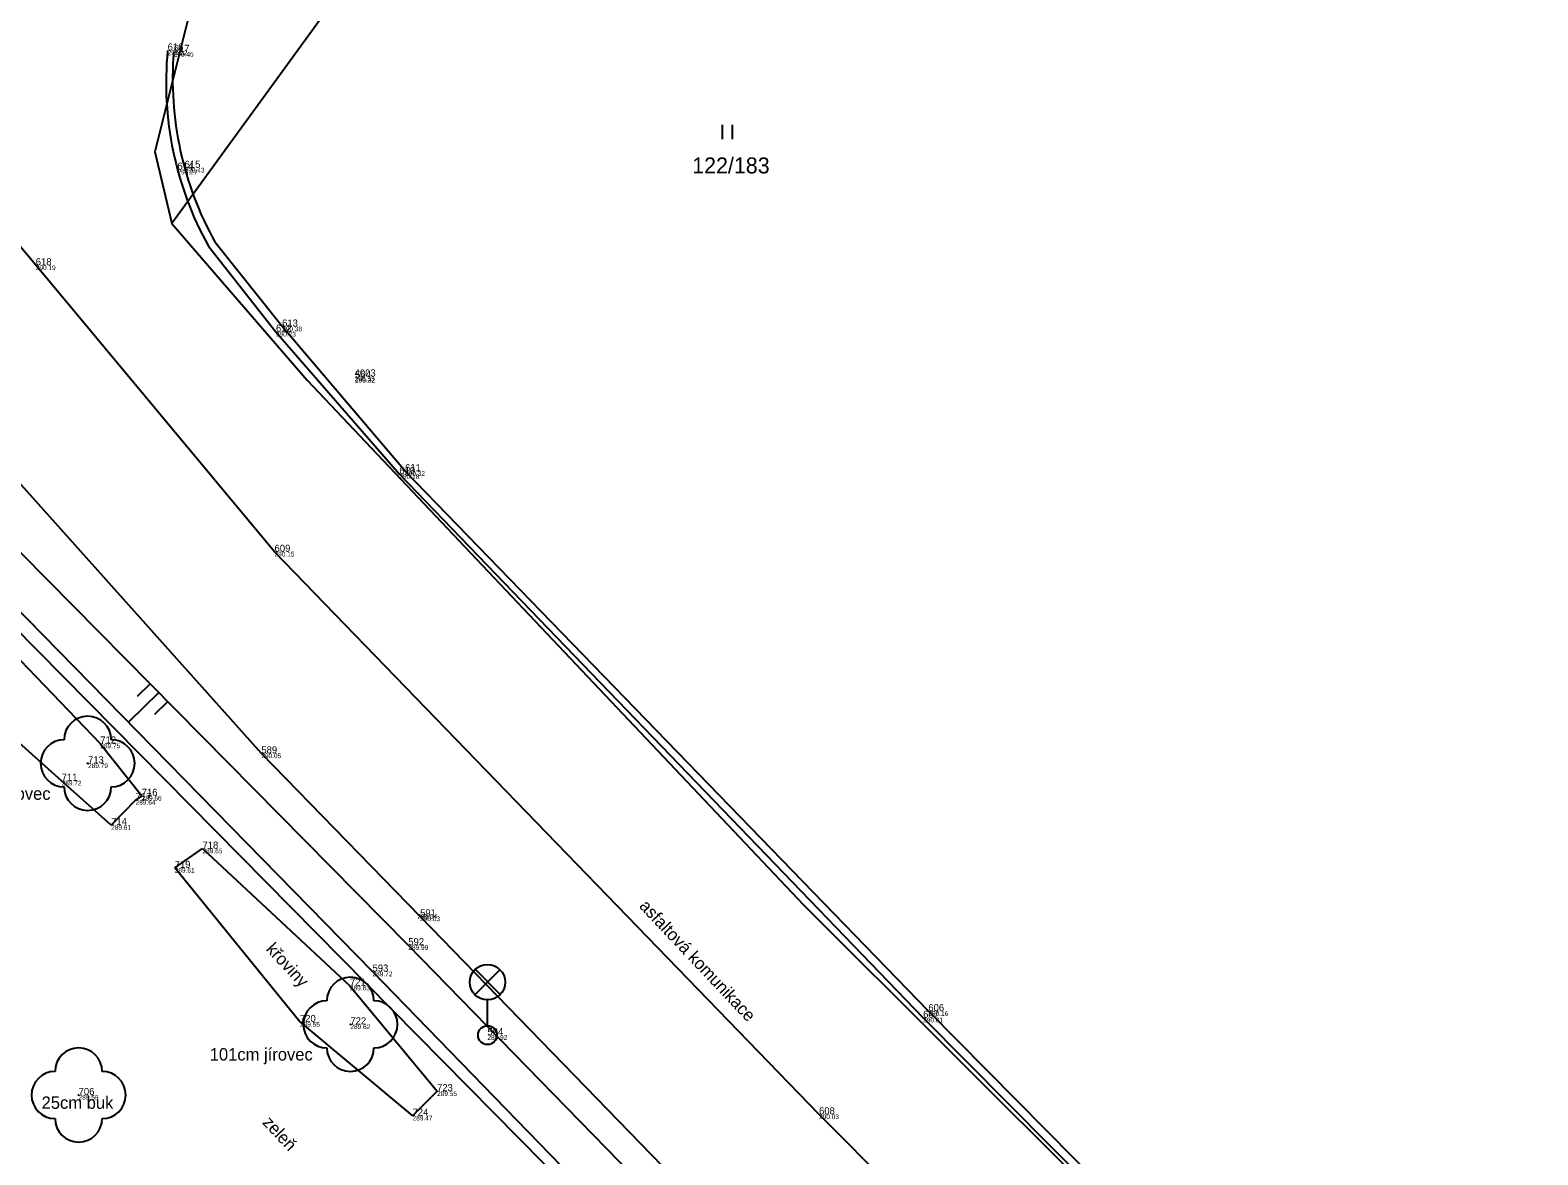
# Model space of a CAD drawing. Extents: x -805057 to -804930, y -994399 to -994240.
# Drawn here: x -804979.61 to -804947.6, y -994315.23 to -994291.36 of the extents above; entities that cross this region are included whole.
import ezdxf

# ---------------------------------------------------------------- set-up
doc = ezdxf.new("R2010")
doc.units = 0
for name, color, linetype in [('bod cislo', 7, 'Continuous'), ('bod pozice', 7, 'Continuous'), ('bod výška', 7, 'Continuous'), ('Katastralni mapa', 7, 'Continuous'), ('komunikace', 7, 'Continuous'), ('lampa', 7, 'Continuous'), ('plot', 7, 'Continuous'), ('popis', 7, 'Continuous'), ('strom', 7, 'Continuous'), ('svah', 7, 'Continuous'), ('šrafy', 7, 'Continuous')]:
    doc.layers.add(name, color=color, linetype=linetype)

msp = doc.modelspace()

# ---------------------------------------------------------------- linework, layer by layer
at = {"layer": 'bod pozice'}
for p, q in [((-804976.69, -994291.79), (-804976.69, -994291.79)), ((-804976.56, -994291.82), (-804976.56, -994291.82)), ((-804976.48, -994294.32), (-804976.48, -994294.32)), ((-804976.33, -994294.28), (-804976.33, -994294.28)), ((-804979.49, -994296.35), (-804979.49, -994296.35)), ((-804974.39, -994297.76), (-804974.39, -994297.76)), ((-804974.26, -994297.65), (-804974.26, -994297.65)), ((-804972.72, -994298.71), (-804972.72, -994298.71)), ((-804972.71, -994298.74), (-804972.71, -994298.74)), ((-804971.77, -994300.78), (-804971.77, -994300.78)), ((-804971.65, -994300.72), (-804971.65, -994300.72)), ((-804974.42, -994302.43), (-804974.42, -994302.43)), ((-804978.12, -994306.5), (-804978.12, -994306.5)), ((-804974.7, -994306.71), (-804974.7, -994306.71)), ((-804978.38, -994306.92), (-804978.38, -994306.92)), ((-804978.94, -994307.29), (-804978.94, -994307.29)), ((-804977.37, -994307.7), (-804977.37, -994307.7)), ((-804977.24, -994307.61), (-804977.24, -994307.61)), ((-804977.89, -994308.23), (-804977.89, -994308.23)), ((-804975.95, -994308.73), (-804975.95, -994308.73)), ((-804976.54, -994309.14), (-804976.54, -994309.14)), ((-804971.33, -994310.17), (-804971.33, -994310.17)), ((-804971.58, -994310.78), (-804971.58, -994310.78)), ((-804972.34, -994311.34), (-804972.34, -994311.34)), ((-804972.82, -994311.64), (-804972.82, -994311.64)), ((-804960.65, -994312.32), (-804960.65, -994312.32)), ((-804960.54, -994312.18), (-804960.54, -994312.18)), ((-804973.88, -994312.41), (-804973.88, -994312.41)), ((-804972.81, -994312.46), (-804972.81, -994312.46)), ((-804969.9, -994312.69), (-804969.9, -994312.69)), ((-804970.97, -994313.88), (-804970.97, -994313.88)), ((-804978.58, -994313.96), (-804978.58, -994313.96)), ((-804971.49, -994314.4), (-804971.49, -994314.4)), ((-804962.86, -994314.37), (-804962.86, -994314.37))]:
    msp.add_line(p, q, dxfattribs=at)
at = {"layer": 'Katastralni mapa'}
for points in [[(-804950.9, -994260.129), (-804976.6, -994295.46)], [(-804976.25, -994291.08), (-804976.96, -994293.94), (-804976.6, -994295.46)], [(-804964.907, -994293.67), (-804964.907, -994293.37)], [(-804964.7, -994293.67), (-804964.7, -994293.37)], [(-804976.6, -994295.46), (-804973.73, -994298.79), (-804963.19, -994309.92)], [(-804953.13, -994331.19), (-804983.74, -994300.19)], [(-804963.19, -994309.92), (-804950.9, -994322.183)]]:
    msp.add_lwpolyline(points, dxfattribs=at)
at = {"layer": 'komunikace'}
for p, q in [((-804979.49, -994296.35), (-804983.16, -994291.96)), ((-804975.825, -994295.944), (-804974.39, -994297.76)), ((-804974.26, -994297.65), (-804975.68, -994295.865)), ((-804974.42, -994302.43), (-804979.49, -994296.35)), ((-804974.39, -994297.76), (-804971.77, -994300.78)), ((-804971.65, -994300.72), (-804974.26, -994297.65)), ((-804974.7, -994306.71), (-804981.23, -994299.41)), ((-804971.77, -994300.78), (-804960.65, -994312.32)), ((-804960.54, -994312.18), (-804971.65, -994300.72)), ((-804962.86, -994314.37), (-804974.42, -994302.43)), ((-804971.33, -994310.17), (-804974.7, -994306.71)), ((-804961.4, -994320.39), (-804971.33, -994310.17)), ((-804960.65, -994312.32), (-804951.51, -994321.52)), ((-804951.4, -994321.41), (-804960.54, -994312.18)), ((-804947.6, -994329.67), (-804962.86, -994314.37))]:
    msp.add_line(p, q, dxfattribs=at)
for centre, major_axis, ratio, start_param, end_param in [((-804969.563, -994292.475), (-5.765, 4.247), 0.999658, 0.539342, 1.141067), ((-804969.491, -994292.399), (-3.36, -6.247), 0.999893, 5.124013, 5.716263)]:
    msp.add_ellipse(centre, major_axis=major_axis, ratio=ratio, start_param=start_param, end_param=end_param, dxfattribs=at)
at = {"layer": 'lampa'}
for p, q in [((-804970.164, -994311.828), (-804969.636, -994311.3)), ((-804970.164, -994311.828), (-804969.636, -994311.3)), ((-804969.628, -994311.825), (-804970.156, -994311.296)), ((-804969.628, -994311.825), (-804970.156, -994311.296)), ((-804969.9, -994312.49), (-804969.9, -994311.94)), ((-804969.9, -994312.49), (-804969.9, -994311.94))]:
    msp.add_line(p, q, dxfattribs=at)
for centre, radius in [((-804969.9, -994311.565), 0.375), ((-804969.9, -994311.565), 0.375), ((-804969.9, -994312.69), 0.2), ((-804969.9, -994312.69), 0.2)]:
    msp.add_circle(centre, radius, dxfattribs=at)
at = {"layer": 'plot'}
for p, q in [((-804972.34, -994311.34), (-804983.01, -994300.45)), ((-804962.76, -994321.19), (-804972.34, -994311.34))]:
    msp.add_line(p, q, dxfattribs=at)
at = {"layer": 'strom'}
for p, q in [((-804982.5, -994301.95), (-804978.12, -994306.5)), ((-804978.94, -994307.29), (-804982.6, -994304.03)), ((-804978.12, -994306.5), (-804977.24, -994307.61)), ((-804977.89, -994308.23), (-804978.94, -994307.29)), ((-804977.37, -994307.7), (-804977.89, -994308.23)), ((-804977.24, -994307.61), (-804977.37, -994307.7)), ((-804976.54, -994309.14), (-804975.95, -994308.73)), ((-804975.95, -994308.73), (-804972.82, -994311.64)), ((-804973.88, -994312.41), (-804976.54, -994309.14)), ((-804972.82, -994311.64), (-804970.97, -994313.88)), ((-804973.88, -994312.41), (-804971.49, -994314.4)), ((-804970.97, -994313.88), (-804971.49, -994314.4))]:
    msp.add_line(p, q, dxfattribs=at)
for centre in [(-804978.388, -994306.92), (-804972.81, -994312.46), (-804978.58, -994313.96)]:
    msp.add_circle(centre, 0.0005, dxfattribs=at)
for centre, start, end in [((-804978.388, -994306.42), 0, 180), ((-804978.888, -994306.92), 90, 270), ((-804977.888, -994306.92), 270, 90), ((-804978.388, -994307.42), 180, 360), ((-804972.81, -994311.96), 0, 180), ((-804973.31, -994312.46), 90, 270), ((-804972.31, -994312.46), 270, 90), ((-804978.58, -994313.46), 0, 180), ((-804972.81, -994312.96), 180, 360), ((-804979.08, -994313.96), 90, 270), ((-804978.08, -994313.96), 270, 90), ((-804978.58, -994314.46), 180, 360)]:
    msp.add_arc(centre, 0.5, start, end, dxfattribs=at)
at = {"layer": 'svah'}
for p, q in [((-804971.58, -994310.78), (-804982.17, -994300.06)), ((-804961.78, -994320.82), (-804971.58, -994310.78))]:
    msp.add_line(p, q, dxfattribs=at)
at = {"layer": 'šrafy'}
for p, q in [((-804977.062, -994305.231), (-804977.339, -994305.499)), ((-804976.875, -994305.42), (-804977.524, -994306.049)), ((-804976.687, -994305.61), (-804976.968, -994305.883))]:
    msp.add_line(p, q, dxfattribs=at)

# ---------------------------------------------------------------- texts
at = {"layer": 'bod cislo'}
for s, p in [('616    ', (-804976.69, -994291.79)), ('617    ', (-804976.56, -994291.82)), ('614    ', (-804976.48, -994294.32)), ('615    ', (-804976.33, -994294.28)), ('618    ', (-804979.49, -994296.35)), ('612    ', (-804974.39, -994297.76)), ('613    ', (-804974.26, -994297.65)), ('4003    ', (-804972.72, -994298.71)), ('564    ', (-804972.71, -994298.74)), ('610    ', (-804971.77, -994300.78)), ('611    ', (-804971.65, -994300.72)), ('609    ', (-804974.42, -994302.43)), ('712    ', (-804978.12, -994306.5)), ('589    ', (-804974.7, -994306.71)), ('713    ', (-804978.38, -994306.92)), ('711    ', (-804978.94, -994307.29)), ('716    ', (-804977.24, -994307.61)), ('717    ', (-804977.37, -994307.7)), ('714    ', (-804977.89, -994308.23)), ('718    ', (-804975.95, -994308.73)), ('719    ', (-804976.54, -994309.14)), ('591    ', (-804971.33, -994310.17)), ('592    ', (-804971.58, -994310.78)), ('593    ', (-804972.34, -994311.34)), ('721    ', (-804972.82, -994311.64)), ('606    ', (-804960.54, -994312.18)), ('720    ', (-804973.88, -994312.41)), ('722    ', (-804972.81, -994312.46)), ('607    ', (-804960.65, -994312.32)), ('594    ', (-804969.9, -994312.69)), ('706    ', (-804978.58, -994313.96)), ('723    ', (-804970.97, -994313.88)), ('724    ', (-804971.49, -994314.4)), ('608    ', (-804962.86, -994314.37))]:
    msp.add_text(s, height=0.15, dxfattribs=at).set_placement(p)
at = {"layer": 'bod výška'}
for s, p in [('290.32  ', (-804976.69, -994291.89)), ('290.45  ', (-804976.56, -994291.92)), ('290.27  ', (-804976.48, -994294.42)), ('290.43  ', (-804976.33, -994294.38)), ('290.19  ', (-804979.49, -994296.45)), ('290.23  ', (-804974.39, -994297.86)), ('290.38  ', (-804974.26, -994297.75)), ('290.33  ', (-804972.72, -994298.81)), ('290.32  ', (-804972.71, -994298.84)), ('290.18  ', (-804971.77, -994300.88)), ('290.32  ', (-804971.65, -994300.82)), ('290.15  ', (-804974.42, -994302.53)), ('289.75  ', (-804978.12, -994306.6)), ('290.05  ', (-804974.7, -994306.81)), ('289.79  ', (-804978.38, -994307.02)), ('289.72  ', (-804978.94, -994307.39)), ('289.64  ', (-804977.37, -994307.8)), ('289.66  ', (-804977.24, -994307.71)), ('289.61  ', (-804977.89, -994308.33)), ('289.65  ', (-804975.95, -994308.83)), ('289.61  ', (-804976.54, -994309.24)), ('290.04  ', (-804971.39, -994310.22)), ('290.03  ', (-804971.33, -994310.27)), ('289.99  ', (-804971.58, -994310.88)), ('289.72  ', (-804972.34, -994311.44)), ('289.63  ', (-804972.82, -994311.74)), ('290.01  ', (-804960.65, -994312.42)), ('290.16  ', (-804960.54, -994312.28)), ('289.55  ', (-804973.88, -994312.51)), ('289.62  ', (-804972.81, -994312.56)), ('289.92  ', (-804969.9, -994312.79)), ('289.55  ', (-804970.97, -994313.98)), ('289.59  ', (-804978.58, -994314.06)), ('289.47  ', (-804971.49, -994314.5)), ('290.03  ', (-804962.86, -994314.47))]:
    msp.add_text(s, height=0.1, dxfattribs=at).set_placement(p)
at = {"layer": 'Katastralni mapa'}
msp.add_text('122/183', height=0.34, dxfattribs=at).set_placement((-804965.553, -994294.4))
at = {"layer": 'popis'}
for s, height, p in [('100cm jírovec', 0.26289, (-804981.363, -994307.694)), ('101cm jírovec', 0.26289, (-804975.797, -994313.228)), ('25cm buk', 0.2629, (-804979.366, -994314.253))]:
    msp.add_text(s, height=height, dxfattribs=at).set_placement(p)
for s, height, rotation, p in [('asfaltová komunikace', 0.26289, 313.3291, (-804966.693, -994309.965)), ('křoviny', 0.2629, 312.8096, (-804974.618, -994310.877)), ('zeleň', 0.2629, 313.0307, (-804974.691, -994314.557))]:
    msp.add_text(s, height=height, rotation=rotation, dxfattribs=at).set_placement(p)

doc.saveas('drawing.dxf')
